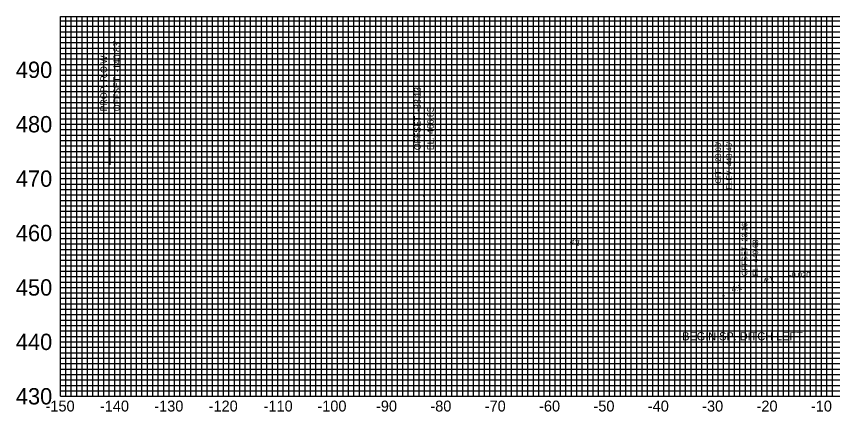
# Model space of a CAD drawing. Extents: x -158 to 158, y 423 to 504.
# Drawn here: x -158.1 to -7.9, y 427.2 to 499.8 of the extents above; entities that cross this region are included whole.
import ezdxf

# ---------------------------------------------------------------- set-up
doc = ezdxf.new("R2010")
doc.units = 0
for name, color, linetype in [('_CIVIL_CONSTRUCTION', 7, 'Continuous'), ('DES - ROW - Linework', 7, 'Continuous'), ('DES - SHEET - Light Grid', 7, 'Continuous'), ('DES - SHEET - Linework', 7, 'Continuous'), ('DES - XS - Proposed - Finished Grade Slopes Text', 7, 'Continuous'), ('DES - XS - Proposed - Text', 7, 'Continuous')]:
    doc.layers.add(name, color=color, linetype=linetype)

msp = doc.modelspace()

# ---------------------------------------------------------------- linework, layer by layer
at = {"layer": '_CIVIL_CONSTRUCTION'}
for centre in [(-83.13, 466.83), (-28.03, 448.46)]:
    msp.add_circle(centre, 0.05, dxfattribs=at)
at = {"layer": 'DES - ROW - Linework'}
msp.add_line((-140.83, 472.54), (-140.83, 477.46), dxfattribs=at)
at = {"layer": 'DES - SHEET - Light Grid'}
for p, q in [((-150, 499), (150, 499)), ((-150, 499), (150, 499)), ((-149, 430), (-149, 499.82)), ((-149, 430), (-149, 499.82)), ((-148, 430), (-148, 499.82)), ((-148, 430), (-148, 499.82)), ((-147, 430), (-147, 499.82)), ((-147, 430), (-147, 499.82)), ((-146, 430), (-146, 499.82)), ((-146, 430), (-146, 499.82)), ((-145, 430), (-145, 499.82)), ((-145, 430), (-145, 499.82)), ((-144, 430), (-144, 499.82)), ((-144, 430), (-144, 499.82)), ((-143, 430), (-143, 499.82)), ((-143, 430), (-143, 499.82)), ((-142, 430), (-142, 499.82)), ((-142, 430), (-142, 499.82)), ((-141, 430), (-141, 499.82)), ((-141, 430), (-141, 499.82)), ((-139, 430), (-139, 499.82)), ((-139, 430), (-139, 499.82)), ((-138, 430), (-138, 499.82)), ((-138, 430), (-138, 499.82)), ((-137, 430), (-137, 499.82)), ((-137, 430), (-137, 499.82)), ((-136, 430), (-136, 499.82)), ((-136, 430), (-136, 499.82)), ((-135, 430), (-135, 499.82)), ((-135, 430), (-135, 499.82)), ((-134, 430), (-134, 499.82)), ((-134, 430), (-134, 499.82)), ((-133, 430), (-133, 499.82)), ((-133, 430), (-133, 499.82)), ((-132, 430), (-132, 499.82)), ((-132, 430), (-132, 499.82)), ((-131, 430), (-131, 499.82)), ((-131, 430), (-131, 499.82)), ((-129, 430), (-129, 499.82)), ((-129, 430), (-129, 499.82)), ((-128, 430), (-128, 499.82)), ((-128, 430), (-128, 499.82)), ((-127, 430), (-127, 499.82)), ((-127, 430), (-127, 499.82)), ((-126, 430), (-126, 499.82)), ((-126, 430), (-126, 499.82)), ((-125, 430), (-125, 499.82)), ((-125, 430), (-125, 499.82)), ((-124, 430), (-124, 499.82)), ((-124, 430), (-124, 499.82)), ((-123, 430), (-123, 499.82)), ((-123, 430), (-123, 499.82)), ((-122, 430), (-122, 499.82)), ((-122, 430), (-122, 499.82)), ((-121, 430), (-121, 499.82)), ((-121, 430), (-121, 499.82)), ((-119, 430), (-119, 499.82)), ((-119, 430), (-119, 499.82)), ((-118, 430), (-118, 499.82)), ((-118, 430), (-118, 499.82)), ((-117, 430), (-117, 499.82)), ((-117, 430), (-117, 499.82)), ((-116, 430), (-116, 499.82)), ((-116, 430), (-116, 499.82)), ((-115, 430), (-115, 499.82)), ((-115, 430), (-115, 499.82)), ((-114, 430), (-114, 499.82)), ((-114, 430), (-114, 499.82)), ((-113, 430), (-113, 499.82)), ((-113, 430), (-113, 499.82)), ((-112, 430), (-112, 499.82)), ((-112, 430), (-112, 499.82)), ((-111, 430), (-111, 499.82)), ((-111, 430), (-111, 499.82)), ((-109, 430), (-109, 499.82)), ((-109, 430), (-109, 499.82)), ((-108, 430), (-108, 499.82)), ((-108, 430), (-108, 499.82)), ((-107, 430), (-107, 499.82)), ((-107, 430), (-107, 499.82)), ((-106, 430), (-106, 499.82)), ((-106, 430), (-106, 499.82)), ((-105, 430), (-105, 499.82)), ((-105, 430), (-105, 499.82)), ((-104, 430), (-104, 499.82)), ((-104, 430), (-104, 499.82)), ((-103, 430), (-103, 499.82)), ((-103, 430), (-103, 499.82)), ((-102, 430), (-102, 499.82)), ((-102, 430), (-102, 499.82)), ((-101, 430), (-101, 499.82)), ((-101, 430), (-101, 499.82)), ((-99, 430), (-99, 499.82)), ((-99, 430), (-99, 499.82)), ((-98, 430), (-98, 499.82)), ((-98, 430), (-98, 499.82)), ((-97, 430), (-97, 499.82)), ((-97, 430), (-97, 499.82)), ((-96, 430), (-96, 499.82)), ((-96, 430), (-96, 499.82)), ((-95, 430), (-95, 499.82)), ((-95, 430), (-95, 499.82)), ((-94, 430), (-94, 499.82)), ((-94, 430), (-94, 499.82)), ((-93, 430), (-93, 499.82)), ((-93, 430), (-93, 499.82)), ((-92, 430), (-92, 499.82)), ((-92, 430), (-92, 499.82)), ((-91, 430), (-91, 499.82)), ((-91, 430), (-91, 499.82)), ((-89, 430), (-89, 499.82)), ((-89, 430), (-89, 499.82)), ((-88, 430), (-88, 499.82)), ((-88, 430), (-88, 499.82)), ((-87, 430), (-87, 499.82)), ((-87, 430), (-87, 499.82)), ((-86, 430), (-86, 499.82)), ((-86, 430), (-86, 499.82)), ((-85, 430), (-85, 499.82)), ((-85, 430), (-85, 499.82)), ((-84, 430), (-84, 499.82)), ((-84, 430), (-84, 499.82)), ((-83, 430), (-83, 499.82)), ((-83, 430), (-83, 499.82)), ((-82, 430), (-82, 499.82)), ((-82, 430), (-82, 499.82)), ((-81, 430), (-81, 499.82)), ((-81, 430), (-81, 499.82)), ((-79, 430), (-79, 499.82)), ((-79, 430), (-79, 499.82)), ((-78, 430), (-78, 499.82)), ((-78, 430), (-78, 499.82)), ((-77, 430), (-77, 499.82)), ((-77, 430), (-77, 499.82)), ((-76, 430), (-76, 499.82)), ((-76, 430), (-76, 499.82)), ((-75, 430), (-75, 499.82)), ((-75, 430), (-75, 499.82)), ((-74, 430), (-74, 499.82)), ((-74, 430), (-74, 499.82)), ((-73, 430), (-73, 499.82)), ((-73, 430), (-73, 499.82)), ((-72, 430), (-72, 499.82)), ((-72, 430), (-72, 499.82)), ((-71, 430), (-71, 499.82)), ((-71, 430), (-71, 499.82)), ((-69, 430), (-69, 499.82)), ((-69, 430), (-69, 499.82)), ((-68, 430), (-68, 499.82)), ((-68, 430), (-68, 499.82)), ((-67, 430), (-67, 499.82)), ((-67, 430), (-67, 499.82)), ((-66, 430), (-66, 499.82)), ((-66, 430), (-66, 499.82)), ((-65, 430), (-65, 499.82)), ((-65, 430), (-65, 499.82)), ((-64, 430), (-64, 499.82)), ((-64, 430), (-64, 499.82)), ((-63, 430), (-63, 499.82)), ((-63, 430), (-63, 499.82)), ((-62, 430), (-62, 499.82)), ((-62, 430), (-62, 499.82)), ((-61, 430), (-61, 499.82)), ((-61, 430), (-61, 499.82)), ((-59, 430), (-59, 499.82)), ((-59, 430), (-59, 499.82)), ((-58, 430), (-58, 499.82)), ((-58, 430), (-58, 499.82)), ((-57, 430), (-57, 499.82)), ((-57, 430), (-57, 499.82)), ((-56, 430), (-56, 499.82)), ((-56, 430), (-56, 499.82)), ((-55, 430), (-55, 499.82)), ((-55, 430), (-55, 499.82)), ((-54, 430), (-54, 499.82)), ((-54, 430), (-54, 499.82)), ((-53, 430), (-53, 499.82)), ((-53, 430), (-53, 499.82)), ((-52, 430), (-52, 499.82)), ((-52, 430), (-52, 499.82)), ((-51, 430), (-51, 499.82)), ((-51, 430), (-51, 499.82)), ((-49, 430), (-49, 499.82)), ((-49, 430), (-49, 499.82)), ((-48, 430), (-48, 499.82)), ((-48, 430), (-48, 499.82)), ((-47, 430), (-47, 499.82)), ((-47, 430), (-47, 499.82)), ((-46, 430), (-46, 499.82)), ((-46, 430), (-46, 499.82)), ((-45, 430), (-45, 499.82)), ((-45, 430), (-45, 499.82)), ((-44, 430), (-44, 499.82)), ((-44, 430), (-44, 499.82)), ((-43, 430), (-43, 499.82)), ((-43, 430), (-43, 499.82)), ((-42, 430), (-42, 499.82)), ((-42, 430), (-42, 499.82)), ((-41, 430), (-41, 499.82)), ((-41, 430), (-41, 499.82)), ((-39, 430), (-39, 499.82)), ((-39, 430), (-39, 499.82)), ((-38, 430), (-38, 499.82)), ((-38, 430), (-38, 499.82)), ((-37, 430), (-37, 499.82)), ((-37, 430), (-37, 499.82)), ((-36, 430), (-36, 499.82)), ((-36, 430), (-36, 499.82)), ((-35, 430), (-35, 499.82)), ((-35, 430), (-35, 499.82)), ((-34, 430), (-34, 499.82)), ((-34, 430), (-34, 499.82)), ((-33, 430), (-33, 499.82)), ((-33, 430), (-33, 499.82)), ((-32, 430), (-32, 499.82)), ((-32, 430), (-32, 499.82)), ((-31, 430), (-31, 499.82)), ((-31, 430), (-31, 499.82)), ((-29, 430), (-29, 499.82)), ((-29, 430), (-29, 499.82)), ((-28, 430), (-28, 499.82)), ((-28, 430), (-28, 499.82)), ((-27, 430), (-27, 499.82)), ((-27, 430), (-27, 499.82)), ((-26, 430), (-26, 499.82)), ((-26, 430), (-26, 499.82)), ((-25, 430), (-25, 499.82)), ((-25, 430), (-25, 499.82)), ((-24, 430), (-24, 499.82)), ((-24, 430), (-24, 499.82)), ((-23, 430), (-23, 499.82)), ((-23, 430), (-23, 499.82)), ((-22, 430), (-22, 499.82)), ((-22, 430), (-22, 499.82)), ((-21, 430), (-21, 499.82)), ((-21, 430), (-21, 499.82)), ((-19, 430), (-19, 499.82)), ((-19, 430), (-19, 499.82)), ((-18, 430), (-18, 499.82)), ((-18, 430), (-18, 499.82)), ((-17, 430), (-17, 499.82)), ((-17, 430), (-17, 499.82)), ((-16, 430), (-16, 499.82)), ((-16, 430), (-16, 499.82)), ((-15, 430), (-15, 499.82)), ((-15, 430), (-15, 499.82)), ((-14, 430), (-14, 499.82)), ((-14, 430), (-14, 499.82)), ((-13, 430), (-13, 499.82)), ((-13, 430), (-13, 499.82)), ((-12, 430), (-12, 499.82)), ((-12, 430), (-12, 499.82)), ((-11, 430), (-11, 499.82)), ((-11, 430), (-11, 499.82)), ((-9, 430), (-9, 499.82)), ((-9, 430), (-9, 499.82)), ((-8, 430), (-8, 499.82)), ((-8, 430), (-8, 499.82)), ((-150, 498), (150, 498)), ((-150, 498), (150, 498)), ((-150, 497), (150, 497)), ((-150, 497), (150, 497)), ((-150, 496), (150, 496)), ((-150, 496), (150, 496)), ((-150, 495), (150, 495)), ((-150, 495), (150, 495)), ((-150, 494), (150, 494)), ((-150, 494), (150, 494)), ((-150, 493), (150, 493)), ((-150, 493), (150, 493)), ((-150, 492), (150, 492)), ((-150, 492), (150, 492)), ((-150, 491), (150, 491)), ((-150, 491), (150, 491)), ((-150, 489), (150, 489)), ((-150, 489), (150, 489)), ((-150, 488), (150, 488)), ((-150, 488), (150, 488)), ((-150, 487), (150, 487)), ((-150, 487), (150, 487)), ((-150, 486), (150, 486)), ((-150, 486), (150, 486)), ((-150, 485), (150, 485)), ((-150, 485), (150, 485)), ((-150, 484), (150, 484)), ((-150, 484), (150, 484)), ((-150, 483), (150, 483)), ((-150, 483), (150, 483)), ((-150, 482), (150, 482)), ((-150, 482), (150, 482)), ((-150, 481), (150, 481)), ((-150, 481), (150, 481)), ((-150, 479), (150, 479)), ((-150, 479), (150, 479)), ((-150, 478), (150, 478)), ((-150, 478), (150, 478)), ((-150, 477), (150, 477)), ((-150, 477), (150, 477)), ((-150, 476), (150, 476)), ((-150, 476), (150, 476)), ((-150, 475), (150, 475)), ((-150, 475), (150, 475)), ((-150, 474), (150, 474)), ((-150, 474), (150, 474)), ((-150, 473), (150, 473)), ((-150, 473), (150, 473)), ((-150, 472), (150, 472)), ((-150, 472), (150, 472)), ((-150, 471), (150, 471)), ((-150, 471), (150, 471)), ((-150, 469), (150, 469)), ((-150, 469), (150, 469)), ((-150, 468), (150, 468)), ((-150, 468), (150, 468)), ((-150, 467), (150, 467)), ((-150, 467), (150, 467)), ((-150, 466), (150, 466)), ((-150, 466), (150, 466)), ((-150, 465), (150, 465)), ((-150, 465), (150, 465)), ((-150, 464), (150, 464)), ((-150, 464), (150, 464)), ((-150, 463), (150, 463)), ((-150, 463), (150, 463)), ((-150, 462), (150, 462)), ((-150, 462), (150, 462)), ((-150, 461), (150, 461)), ((-150, 461), (150, 461)), ((-150, 459), (150, 459)), ((-150, 459), (150, 459)), ((-150, 458), (150, 458)), ((-150, 458), (150, 458)), ((-150, 457), (150, 457)), ((-150, 457), (150, 457)), ((-150, 456), (150, 456)), ((-150, 456), (150, 456)), ((-150, 455), (150, 455)), ((-150, 455), (150, 455)), ((-150, 454), (150, 454)), ((-150, 454), (150, 454)), ((-150, 453), (150, 453)), ((-150, 453), (150, 453)), ((-150, 452), (150, 452)), ((-150, 452), (150, 452)), ((-150, 451), (150, 451)), ((-150, 451), (150, 451)), ((-150, 449), (150, 449)), ((-150, 449), (150, 449)), ((-150, 448), (150, 448)), ((-150, 448), (150, 448)), ((-150, 447), (150, 447)), ((-150, 447), (150, 447)), ((-150, 446), (150, 446)), ((-150, 446), (150, 446)), ((-150, 445), (150, 445)), ((-150, 445), (150, 445)), ((-150, 444), (150, 444)), ((-150, 444), (150, 444)), ((-150, 443), (150, 443)), ((-150, 443), (150, 443)), ((-150, 442), (150, 442)), ((-150, 442), (150, 442)), ((-150, 441), (150, 441)), ((-150, 441), (150, 441)), ((-150, 439), (150, 439)), ((-150, 439), (150, 439)), ((-150, 438), (150, 438)), ((-150, 438), (150, 438)), ((-150, 437), (150, 437)), ((-150, 437), (150, 437)), ((-150, 436), (150, 436)), ((-150, 436), (150, 436)), ((-150, 435), (150, 435)), ((-150, 435), (150, 435)), ((-150, 434), (150, 434)), ((-150, 434), (150, 434)), ((-150, 433), (150, 433)), ((-150, 433), (150, 433)), ((-150, 432), (150, 432)), ((-150, 432), (150, 432)), ((-150, 431), (150, 431)), ((-150, 431), (150, 431))]:
    msp.add_line(p, q, dxfattribs=at)
at = {"layer": 'DES - SHEET - Linework'}
for p, q in [((-150, 499.82), (150, 499.82)), ((-150, 430), (-150, 499.82)), ((-150, 499.82), (150, 499.82)), ((-150, 430), (-150, 499.82)), ((-140, 430), (-140, 499.82)), ((-140, 430), (-140, 499.82)), ((-130, 430), (-130, 499.82)), ((-130, 430), (-130, 499.82)), ((-120, 430), (-120, 499.82)), ((-120, 430), (-120, 499.82)), ((-110, 430), (-110, 499.82)), ((-110, 430), (-110, 499.82)), ((-100, 430), (-100, 499.82)), ((-100, 430), (-100, 499.82)), ((-90, 430), (-90, 499.82)), ((-90, 430), (-90, 499.82)), ((-80, 430), (-80, 499.82)), ((-80, 430), (-80, 499.82)), ((-70, 430), (-70, 499.82)), ((-70, 430), (-70, 499.82)), ((-60, 430), (-60, 499.82)), ((-60, 430), (-60, 499.82)), ((-50, 430), (-50, 499.82)), ((-50, 430), (-50, 499.82)), ((-40, 430), (-40, 499.82)), ((-40, 430), (-40, 499.82)), ((-30, 430), (-30, 499.82)), ((-30, 430), (-30, 499.82)), ((-20, 430), (-20, 499.82)), ((-20, 430), (-20, 499.82)), ((-10, 430), (-10, 499.82)), ((-10, 430), (-10, 499.82)), ((-150, 490), (150, 490)), ((-150, 490), (150, 490)), ((-150, 480), (150, 480)), ((-150, 480), (150, 480)), ((-150, 470), (150, 470)), ((-150, 470), (150, 470)), ((-150, 460), (150, 460)), ((-150, 460), (150, 460)), ((-150, 450), (150, 450)), ((-150, 450), (150, 450)), ((-150, 440), (150, 440)), ((-150, 440), (150, 440)), ((-150, 430), (150, 430)), ((-150, 430), (150, 430))]:
    msp.add_line(p, q, dxfattribs=at)

# ---------------------------------------------------------------- texts
at = {"layer": 'DES - ROW - Linework'}
for s, p in [("OFFSET: -140.83'", (-139.03, 482.38)), ('PROP. R.O.W.', (-141.43, 482.38))]:
    msp.add_text(s, height=1.2, rotation=90, dxfattribs=at).set_placement(p)
at = {"layer": 'DES - XS - Proposed - Finished Grade Slopes Text'}
for s, height, rotation, p in [("-83.13'", 1.2, 90, (-83.73, 482.28)), ('466.83', 1.2, 90, (-81.33, 478.21)), ('OFFSET ', 1.2, 90, (-83.73, 475.23)), ('EL. ', 1.2, 90, (-81.33, 475.23)), ('3:1', 1, 341.5668, (-56.38, 458.21)), ('4:1', 1, 14.0362, (-20.6, 450.62)), ('4:1', 1, 14.0362, (-20.6, 450.62)), ('-0.020', 1, 1.1458, (-15.95, 451.77)), ('-0.020', 1, 1.1458, (-15.95, 451.77)), ('4:1', 1, 14.0362, (-26.41, 449.17)), ('4:1', 1, 14.0362, (-26.41, 449.17))]:
    msp.add_text(s, height=height, rotation=rotation, dxfattribs=at).set_placement(p)
at = {"layer": 'DES - XS - Proposed - Text'}
for s, height, p in [('490', 3, (-158.19, 488.5)), ('490', 3, (-158.19, 488.5)), ('480', 3, (-158.19, 478.5)), ('480', 3, (-158.19, 478.5)), ('470', 3, (-158.19, 468.5)), ('470', 3, (-158.19, 468.5)), ('460', 3, (-158.19, 458.5)), ('460', 3, (-158.19, 458.5)), ('450', 3, (-158.19, 448.5)), ('450', 3, (-158.19, 448.5)), ('440', 3, (-158.19, 438.5)), ('440', 3, (-158.19, 438.5)), ('BEGIN SP. DITCH LEFT', 1.5, (-35.63, 440.28)), ('430', 3, (-158.19, 428.5)), ('430', 3, (-158.19, 428.5)), ('-150', 2, (-152.73, 427.2)), ('-150', 2, (-152.73, 427.2)), ('-140', 2, (-142.73, 427.2)), ('-140', 2, (-142.73, 427.2)), ('-130', 2, (-132.73, 427.2)), ('-130', 2, (-132.73, 427.2)), ('-120', 2, (-122.73, 427.2)), ('-120', 2, (-122.73, 427.2)), ('-110', 2, (-112.62, 427.2)), ('-110', 2, (-112.62, 427.2)), ('-100', 2, (-102.73, 427.2)), ('-100', 2, (-102.73, 427.2)), ('-90', 2, (-91.95, 427.2)), ('-90', 2, (-91.95, 427.2)), ('-80', 2, (-81.95, 427.2)), ('-80', 2, (-81.95, 427.2)), ('-70', 2, (-71.95, 427.2)), ('-70', 2, (-71.95, 427.2)), ('-60', 2, (-61.95, 427.2)), ('-60', 2, (-61.95, 427.2)), ('-50', 2, (-51.95, 427.2)), ('-50', 2, (-51.95, 427.2)), ('-40', 2, (-41.95, 427.2)), ('-40', 2, (-41.95, 427.2)), ('-30', 2, (-31.95, 427.2)), ('-30', 2, (-31.95, 427.2)), ('-20', 2, (-21.95, 427.2)), ('-20', 2, (-21.95, 427.2)), ('-10', 2, (-11.95, 427.2)), ('-10', 2, (-11.95, 427.2))]:
    msp.add_text(s, height=height, dxfattribs=at).set_placement(p)
for s, p in [("-28.03'", (-28.5, 472.63)), ("448.46'", (-26.5, 472.31)), ('OFF. ', (-28.5, 469.06)), ('ELEV. ', (-26.5, 467.96)), ("-23.16'", (-23.66, 457.96)), ('449.68', (-21.66, 454.57)), ('OFFSET ', (-23.66, 452.08)), ('EL. ', (-21.66, 452.08))]:
    msp.add_text(s, height=1, rotation=90, dxfattribs=at).set_placement(p)

doc.saveas('drawing.dxf')
